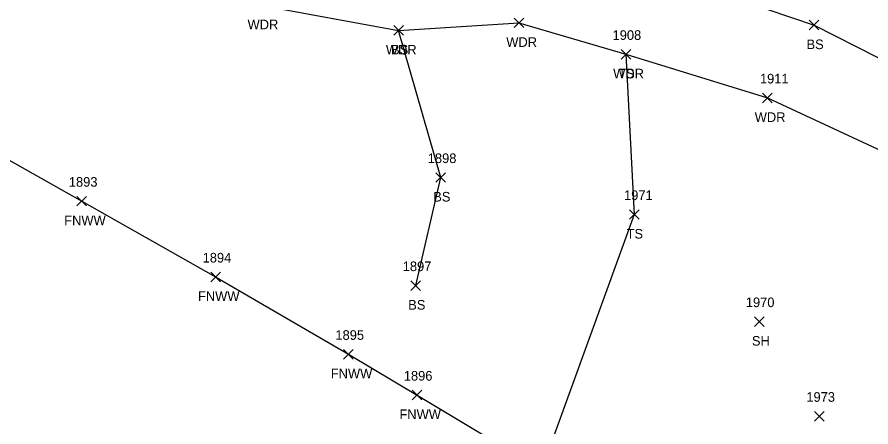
# Model space of a CAD drawing. Extents: x 1629176 to 1637209, y 606063 to 610167.
# Drawn here: x 1630435.7 to 1630613, y 606525.7 to 606610.8 of the extents above; entities that cross this region are included whole.
import ezdxf

# ---------------------------------------------------------------- set-up
doc = ezdxf.new("R2010")
doc.units = 0
for name, color, linetype in [('L_A', 7, 'Continuous'), ('L_I', 7, 'Continuous'), ('L_TIC', 7, 'Continuous'), ('LAWA', 7, 'Continuous'), ('LELB', 7, 'Continuous'), ('LFNC', 7, 'Continuous')]:
    doc.layers.add(name, color=color, linetype=linetype)

msp = doc.modelspace()

# ---------------------------------------------------------------- linework, layer by layer
at = {"layer": 'L_TIC'}
for points in [[(1630538.89, 606608.62), (1630540.89, 606610.62)], [(1630540.89, 606608.62), (1630538.89, 606610.62)], [(1630600.15, 606608.16), (1630602.15, 606610.16)], [(1630602.15, 606608.16), (1630600.15, 606610.16)], [(1630513.89, 606607.05), (1630515.89, 606609.05)], [(1630515.89, 606607.05), (1630513.89, 606609.05)], [(1630513.89, 606607.05), (1630515.89, 606609.05)], [(1630515.89, 606607.05), (1630513.89, 606609.05)], [(1630561.09, 606602.08), (1630563.09, 606604.08)], [(1630563.09, 606602.08), (1630561.09, 606604.08)], [(1630561.09, 606602.08), (1630563.09, 606604.08)], [(1630563.09, 606602.08), (1630561.09, 606604.08)], [(1630590.48, 606593.03), (1630592.48, 606595.03)], [(1630592.48, 606593.03), (1630590.48, 606595.03)], [(1630522.65, 606576.5), (1630524.65, 606578.5)], [(1630524.65, 606576.5), (1630522.65, 606578.5)], [(1630448.11, 606571.58), (1630450.11, 606573.58)], [(1630450.11, 606571.58), (1630448.11, 606573.58)], [(1630562.83, 606568.81), (1630564.83, 606570.81)], [(1630564.83, 606568.81), (1630562.83, 606570.81)], [(1630475.9, 606555.84), (1630477.9, 606557.84)], [(1630477.9, 606555.84), (1630475.9, 606557.84)], [(1630517.44, 606554.05), (1630519.44, 606556.05)], [(1630519.44, 606554.05), (1630517.44, 606556.05)], [(1630588.77, 606546.57), (1630590.77, 606548.57)], [(1630590.77, 606546.57), (1630588.77, 606548.57)], [(1630503.46, 606539.78), (1630505.46, 606541.78)], [(1630505.46, 606539.78), (1630503.46, 606541.78)], [(1630517.72, 606531.31), (1630519.72, 606533.31)], [(1630519.72, 606531.31), (1630517.72, 606533.31)], [(1630601.25, 606526.91), (1630603.25, 606528.91)], [(1630603.25, 606526.91), (1630601.25, 606528.91)]]:
    msp.add_lwpolyline(points, dxfattribs=at)
at = {"layer": 'LAWA'}
msp.add_lwpolyline([(1630297.68, 606682.91), (1630335.71, 606675.48), (1630386.4, 606666.36), (1630422.65, 606653.68), (1630444.38, 606639.08), (1630446.66, 606637.81), (1630486.16, 606613.28), (1630514.89, 606608.05), (1630539.89, 606609.62), (1630562.09, 606603.08), (1630591.48, 606594.03), (1630626, 606578), (1630626.04, 606578.1), (1630670.33, 606553.73), (1630697.07, 606528.38), (1630722.88, 606501.58)], dxfattribs=at)
at = {"layer": 'LELB'}
for points in [[(1630469.72, 606651.64), (1630496.75, 606635.89), (1630520.54, 606626.59), (1630540.08, 606622.19), (1630567.61, 606620.59), (1630601.15, 606609.16), (1630644.49, 606587.12), (1630679, 606566.75), (1630703.09, 606550.33), (1630739.27, 606526.44)], [(1630518.44, 606555.05), (1630523.65, 606577.5), (1630514.89, 606608.05)], [(1630562.09, 606603.08), (1630563.83, 606569.81), (1630544.56, 606516.77)]]:
    msp.add_lwpolyline(points, dxfattribs=at)
at = {"layer": 'LFNC'}
msp.add_lwpolyline([(1630083.24, 606643.38), (1630104.82, 606668.58), (1630132.44, 606699.6), (1630148.03, 606717.8), (1630178.45, 606705.28), (1630206.32, 606692.67), (1630267, 606665.5), (1630297.13, 606649.31), (1630336.07, 606632.29), (1630377.56, 606610.95), (1630421.19, 606588.3), (1630449.11, 606572.58), (1630476.9, 606556.84), (1630504.46, 606540.78), (1630518.72, 606532.31), (1630544.56, 606516.77), (1630586.07, 606490.29), (1630617.62, 606470.71), (1630638.04, 606457.74), (1630683.84, 606426.78)], dxfattribs=at)

# ---------------------------------------------------------------- texts
at = {"layer": 'L_A'}
for s, p in [('WDR', (1630483.53, 606608.28)), ('WDR', (1630537.25, 606604.62)), ('BS', (1630599.59, 606604.16)), ('WDR', (1630512.25, 606603.05)), ('BS', (1630513.33, 606603.05)), ('WDR', (1630559.45, 606598.08)), ('TS', (1630560.5, 606598.08)), ('WDR', (1630588.84, 606589.03)), ('BS', (1630522.09, 606572.5)), ('FNWW', (1630445.46, 606567.58)), ('TS', (1630562.24, 606564.81)), ('FNWW', (1630473.24, 606551.84)), ('BS', (1630516.89, 606550.05)), ('SH', (1630588.26, 606542.57)), ('FNWW', (1630500.81, 606535.78)), ('FNWW', (1630515.07, 606527.31))]:
    msp.add_text(s, height=2, dxfattribs=at).set_placement(p)
at = {"layer": 'L_I'}
for s, p in [('1908', (1630559.32, 606606.08)), ('1908', (1630559.32, 606606.08)), ('1911', (1630589.92, 606597.03)), ('1898', (1630520.95, 606580.5)), ('1893', (1630446.42, 606575.58)), ('1971', (1630561.7, 606572.81)), ('1894', (1630474.2, 606559.84)), ('1897', (1630515.75, 606558.05)), ('1970', (1630586.99, 606550.57)), ('1895', (1630501.77, 606543.78)), ('1896', (1630515.97, 606535.31)), ('1973', (1630599.56, 606530.91))]:
    msp.add_text(s, height=2, dxfattribs=at).set_placement(p)

doc.saveas('drawing.dxf')
